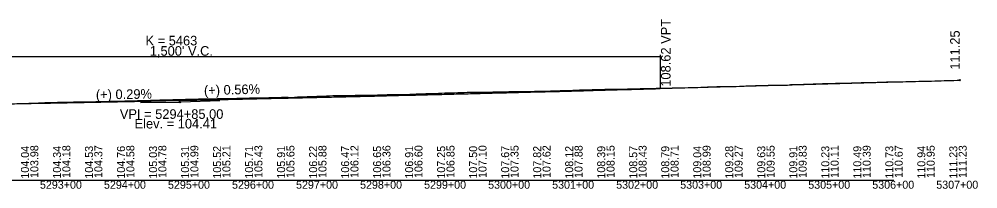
# Model space of a CAD drawing. Extents: x 2121671 to 2169879, y 557274 to 599957.
# Drawn here: x 2158802 to 2160299, y 582173 to 582438 of the extents above; entities that cross this region are included whole.
import ezdxf

# ---------------------------------------------------------------- set-up
doc = ezdxf.new("R2010")
doc.units = 0
for name, color, linetype in [('RD_DDB_GradeTX', 7, 'Continuous'), ('RD_DDB_Profile_EX', 7, 'Continuous'), ('RD_DDB_Profile_Lbl', 7, 'Continuous'), ('RD_DDB_Profile_PR', 7, 'Continuous'), ('RD_DDB_StaTX', 7, 'Continuous'), ('RD_DDB_StripGrade', 7, 'Continuous'), ('RD_DDB_VCLbl', 7, 'Continuous'), ('RD_GPK_Profile_Cell', 7, 'Continuous')]:
    doc.layers.add(name, color=color, linetype=linetype)

msp = doc.modelspace()

# ---------------------------------------------------------------- linework, layer by layer
at = {"layer": 'RD_DDB_GradeTX'}
for p, q in [((2158990.9, 582308), (2159051.9, 582308.9)), ((2159114.9, 582310.6), (2159053.9, 582308.9))]:
    msp.add_line(p, q, dxfattribs=at)
for centre in [(2160270.7, 582343.1), (2159052.9, 582308.9)]:
    msp.add_circle(centre, 1, dxfattribs=at)
at = {"layer": 'RD_DDB_Profile_EX'}
for points in [[(2159986.5, 582335.3), (2159991.5, 582335.2), (2159996.5, 582335.2), (2160001.5, 582335.3), (2160006.5, 582336.1), (2160011.5, 582336.2), (2160016.5, 582336.3), (2160021.5, 582336.5), (2160026.5, 582336.6), (2160031.5, 582336.8), (2160036.5, 582337), (2160041.5, 582337.2), (2160046.5, 582337.3), (2160051.5, 582337.5), (2160056.5, 582337.7), (2160061.5, 582337.8), (2160066.5, 582337.9), (2160071.5, 582338), (2160076.5, 582338.1), (2160081.5, 582338.3), (2160086.5, 582338.4), (2160091.5, 582338.5), (2160096.5, 582338.6), (2160101.5, 582338.7), (2160106.5, 582338.9), (2160111.5, 582338.9), (2160116.5, 582339.2), (2160121.5, 582339.3), (2160126.5, 582339.4), (2160131.5, 582339.5), (2160136.5, 582339.5), (2160141.5, 582339.7), (2160146.5, 582339.9), (2160151.5, 582340), (2160156.5, 582340.2), (2160161.5, 582340.3), (2160166.5, 582340.4), (2160171.5, 582340.5), (2160176.5, 582340.6), (2160181.5, 582340.6), (2160186.5, 582340.7), (2160191.5, 582340.9), (2160196.5, 582341.1), (2160201.5, 582341.2), (2160206.5, 582341.3), (2160211.5, 582341.4), (2160216.5, 582341.5), (2160221.5, 582341.6), (2160226.5, 582341.7), (2160231.5, 582341.9), (2160236.5, 582342.1), (2160241.5, 582342.2), (2160246.5, 582342.3), (2160251.5, 582342.5), (2160256.5, 582342.6), (2160261.5, 582342.7), (2160266.5, 582342.9), (2160270.7, 582343.1)], [(2159486.5, 582323.6), (2159491.5, 582323.7), (2159496.5, 582323.9), (2159501.5, 582324.1), (2159506.5, 582324.2), (2159511.5, 582324.3), (2159516.5, 582324.3), (2159521.5, 582324.3), (2159526.5, 582324.4), (2159531.5, 582324.5), (2159536.5, 582324.5), (2159541.5, 582324.7), (2159546.5, 582325), (2159551.5, 582324.7), (2159556.5, 582324.8), (2159561.5, 582325), (2159566.5, 582325.1), (2159571.5, 582325.3), (2159576.5, 582325.5), (2159581.5, 582325.5), (2159586.5, 582325.1), (2159591.5, 582325.1), (2159596.5, 582325.5), (2159601.5, 582325.5), (2159606.5, 582325.6), (2159611.5, 582325.8), (2159616.5, 582326), (2159621.5, 582325.7), (2159626.5, 582326.1), (2159631.5, 582326.4), (2159636.5, 582326.5), (2159641.5, 582326.6), (2159646.5, 582326.7), (2159651.5, 582326.9), (2159656.5, 582327), (2159661.5, 582327.1), (2159666.5, 582327.4), (2159671.5, 582327.6), (2159676.5, 582327.7), (2159681.5, 582327.9), (2159686.5, 582328), (2159691.5, 582328.2), (2159696.5, 582328.3), (2159701.5, 582328.3), (2159706.5, 582328.4), (2159711.5, 582328.6), (2159716.5, 582328.8), (2159721.5, 582328.8), (2159726.5, 582328.9), (2159731.5, 582329), (2159736.5, 582329), (2159741.5, 582329), (2159746.5, 582329.2), (2159751.5, 582329.4), (2159756.5, 582329.4), (2159761.5, 582329.4), (2159766.5, 582329.6), (2159771.5, 582329.8), (2159776.5, 582329.9), (2159781.5, 582330), (2159786.5, 582330.1), (2159791.5, 582330.2), (2159796.5, 582330.3), (2159801.5, 582330.3), (2159806.5, 582330.4), (2159811.5, 582330.5), (2159816.5, 582330.7), (2159821.5, 582330.9), (2159826.5, 582331), (2159831.5, 582331.1), (2159836.5, 582331.2), (2159841.5, 582331.3), (2159846.5, 582331.4), (2159851.5, 582331.5), (2159856.5, 582331.6), (2159861.5, 582331.8), (2159866.5, 582332), (2159871.5, 582332.2), (2159876.5, 582332.4), (2159881.5, 582332.6), (2159886.5, 582332.8), (2159891.5, 582332.9), (2159896.5, 582333.1), (2159901.5, 582333.3), (2159906.5, 582333.1), (2159911.5, 582333.1), (2159916.5, 582333.2), (2159921.5, 582333.4), (2159926.5, 582333.5), (2159931.5, 582333.9), (2159936.5, 582334.3), (2159941.5, 582334.4), (2159946.5, 582334.3), (2159951.5, 582334.8), (2159956.5, 582334.7), (2159961.5, 582334.8), (2159966.5, 582334.9), (2159971.5, 582335.1), (2159976.5, 582335.3), (2159981.5, 582335.4), (2159986.5, 582335.3)], [(2158801.5, 582306.7), (2158806.5, 582306.8), (2158811.5, 582306.8), (2158816.5, 582307), (2158821.5, 582307.1), (2158826.5, 582307.3), (2158831.5, 582307.5), (2158836.5, 582307.8), (2158841.5, 582308.1), (2158846.5, 582308.3), (2158851.5, 582308.4), (2158856.5, 582308.4), (2158861.5, 582308.5), (2158866.5, 582308.5), (2158871.5, 582308.6), (2158876.5, 582308.8), (2158881.5, 582308.9), (2158886.5, 582309), (2158891.5, 582309.1), (2158896.5, 582309.1), (2158901.5, 582309.4), (2158906.5, 582309.4), (2158911.5, 582309.4), (2158916.5, 582309.4), (2158921.5, 582309.5), (2158926.5, 582309.7), (2158931.5, 582309.9), (2158936.5, 582309.9), (2158941.5, 582310), (2158946.5, 582310.1), (2158951.5, 582310.3), (2158956.5, 582310.3), (2158961.5, 582310.4), (2158966.5, 582310.6), (2158971.5, 582310.8), (2158976.5, 582310.9), (2158981.5, 582311), (2158986.5, 582311.1)], [(2158986.5, 582311.1), (2158991.5, 582311.2), (2158996.5, 582311.3), (2159001.5, 582311.5), (2159006.5, 582311.6), (2159011.5, 582311.7), (2159016.5, 582311.9), (2159021.5, 582312.1), (2159026.5, 582312.2), (2159031.5, 582312.4), (2159036.5, 582312.5), (2159041.5, 582312.6), (2159046.5, 582312.8), (2159051.5, 582312.9), (2159056.5, 582313), (2159061.5, 582313.2), (2159066.5, 582313.4), (2159071.5, 582313.5), (2159076.5, 582313.6), (2159081.5, 582313.7), (2159086.5, 582313.8), (2159091.5, 582313.9), (2159096.5, 582313.9), (2159101.5, 582313.9), (2159106.5, 582314.1), (2159111.5, 582314.3), (2159116.5, 582314.4), (2159121.5, 582314.5), (2159126.5, 582314.5), (2159131.5, 582314.5), (2159136.5, 582314.5), (2159141.5, 582314.7), (2159146.5, 582314.8), (2159151.5, 582315), (2159156.5, 582315.1), (2159161.5, 582315.2), (2159166.5, 582315.4), (2159171.5, 582315.4), (2159176.5, 582315.2), (2159181.5, 582315.2), (2159186.5, 582315.5), (2159191.5, 582315.9), (2159196.5, 582315.9), (2159201.5, 582315.9), (2159206.5, 582316.1), (2159211.5, 582316.3), (2159216.5, 582316.4), (2159221.5, 582316.3), (2159226.5, 582316), (2159231.5, 582316.7), (2159236.5, 582316.9), (2159241.5, 582317.1), (2159246.5, 582317.2), (2159251.5, 582317.3), (2159256.5, 582317.5), (2159261.5, 582317.7), (2159266.5, 582317.9), (2159271.5, 582318.1), (2159276.5, 582318.3), (2159281.5, 582318.5), (2159286.5, 582318.7), (2159291.5, 582318.9), (2159296.5, 582319.1), (2159301.5, 582318.9), (2159306.5, 582318.9), (2159311.5, 582318.9), (2159316.5, 582319.1), (2159321.5, 582319.3), (2159326.5, 582319.4), (2159331.5, 582319.5), (2159336.5, 582319.5), (2159341.5, 582319.5), (2159346.5, 582319.5), (2159351.5, 582319.7), (2159356.5, 582319.8), (2159361.5, 582320), (2159366.5, 582320.1), (2159371.5, 582320.2), (2159376.5, 582320.4), (2159381.5, 582320.5), (2159386.5, 582320.7), (2159391.5, 582320.7), (2159396.5, 582320.6), (2159401.5, 582320.7), (2159406.5, 582320.9), (2159411.5, 582321.1), (2159416.5, 582321.4), (2159421.5, 582321.5), (2159426.5, 582321.7), (2159431.5, 582321.8), (2159436.5, 582322), (2159441.5, 582322.1), (2159446.5, 582322.3), (2159451.5, 582322.4), (2159456.5, 582322.6), (2159461.5, 582322.8), (2159466.5, 582323), (2159471.5, 582323.2), (2159476.5, 582323.3), (2159481.5, 582323.4), (2159486.5, 582323.6)]]:
    msp.add_lwpolyline(points, dxfattribs=at)
at = {"layer": 'RD_DDB_Profile_PR'}
msp.add_line((2159802.9, 582329.9), (2160270.7, 582343.1), dxfattribs=at)
msp.add_spline([(2158302.9, 582298.2), (2158332.9, 582298.6), (2158362.9, 582299), (2158392.9, 582299.5), (2158422.9, 582299.9), (2158452.9, 582300.4), (2158482.9, 582300.9), (2158512.9, 582301.4), (2158542.9, 582301.9), (2158572.9, 582302.4), (2158602.9, 582302.9), (2158632.9, 582303.4), (2158662.9, 582303.9), (2158692.9, 582304.4), (2158722.9, 582305), (2158752.9, 582305.5), (2158782.9, 582306.1), (2158812.9, 582306.7), (2158842.9, 582307.2), (2158872.9, 582307.8), (2158902.9, 582308.4), (2158932.9, 582309), (2158962.9, 582309.6), (2158992.9, 582310.2), (2159022.9, 582310.8), (2159052.9, 582311.5), (2159082.9, 582312.1), (2159112.9, 582312.8), (2159142.9, 582313.4), (2159172.9, 582314.1), (2159202.9, 582314.8), (2159232.9, 582315.4), (2159262.9, 582316.1), (2159292.9, 582316.8), (2159322.9, 582317.5), (2159352.9, 582318.2), (2159382.9, 582319), (2159412.9, 582319.7), (2159442.9, 582320.4), (2159472.9, 582321.2), (2159502.9, 582321.9), (2159532.9, 582322.7), (2159562.9, 582323.5), (2159592.9, 582324.3), (2159622.9, 582325), (2159652.9, 582325.8), (2159682.9, 582326.6), (2159712.9, 582327.5), (2159742.9, 582328.3), (2159772.9, 582329.1), (2159802.9, 582329.9)], degree=3, dxfattribs=at)
at = {"layer": 'RD_DDB_VCLbl'}
for p, q in [((2158302.9, 582379.9), (2159802.9, 582379.9)), ((2159802.9, 582382.4), (2159802.9, 582329.9))]:
    msp.add_line(p, q, dxfattribs=at)
at = {"layer": 'RD_GPK_Profile_Cell'}
msp.add_line((2157367.9, 582186.8), (2160167.9, 582186.8), dxfattribs=at)

# ---------------------------------------------------------------- texts
at = {"layer": 'RD_DDB_GradeTX'}
for s, rotation, p in [('(+) 0.29%', 0.8206, (2158921.5, 582313)), ('(+) 0.56%', 1.6068, (2159090.4, 582319.5))]:
    msp.add_text(s, height=15, rotation=rotation, dxfattribs=at).set_placement(p)
at = {"layer": 'RD_DDB_Profile_Lbl'}
msp.add_text('111.25', height=15, rotation=90, dxfattribs=at).set_placement((2160270.7, 582359.4))
for s, p in [('VPI = 5294+85.00', (2158958.8, 582282.6)), ('Elev. = 104.41', (2158981.8, 582267.6))]:
    msp.add_text(s, height=15, dxfattribs=at).set_placement(p)
at = {"layer": 'RD_DDB_StaTX'}
for s, p in [('5293+00', (2158834, 582173.5)), ('5294+00', (2158934, 582173.5)), ('5295+00', (2159034, 582173.5)), ('5296+00', (2159134, 582173.5)), ('5297+00', (2159234, 582173.5)), ('5298+00', (2159334, 582173.5)), ('5299+00', (2159434, 582173.5)), ('5300+00', (2159534, 582173.5)), ('5301+00', (2159634, 582173.5)), ('5302+00', (2159734, 582173.5)), ('5303+00', (2159834, 582173.5)), ('5304+00', (2159934, 582173.5)), ('5305+00', (2160034, 582173.5)), ('5306+00', (2160134, 582173.5)), ('5307+00', (2160234, 582173.5))]:
    msp.add_text(s, height=12.5, dxfattribs=at).set_placement(p)
at = {"layer": 'RD_DDB_StripGrade'}
for s, height, p in [('108.62 VPT', 15, (2159819, 582332.8)), ('104.04', 12.5, (2158816.9, 582189.3)), ('103.98', 12.5, (2158831.5, 582190.3)), ('104.34', 12.5, (2158866.9, 582189.3)), ('104.18', 12.5, (2158881.5, 582190.3)), ('104.53', 12.5, (2158916.9, 582189.3)), ('104.37', 12.5, (2158931.5, 582190.3)), ('104.76', 12.5, (2158966.9, 582189.3)), ('104.58', 12.5, (2158981.5, 582190.3)), ('105.03', 12.5, (2159016.9, 582189.3)), ('104.78', 12.5, (2159031.5, 582190.3)), ('105.31', 12.5, (2159066.9, 582189.3)), ('104.99', 12.5, (2159081.5, 582190.3)), ('105.52', 12.5, (2159116.9, 582189.3)), ('105.21', 12.5, (2159131.5, 582190.3)), ('105.71', 12.5, (2159166.9, 582189.3)), ('105.43', 12.5, (2159181.5, 582190.3)), ('105.91', 12.5, (2159216.9, 582189.3)), ('105.65', 12.5, (2159231.5, 582190.3)), ('106.22', 12.5, (2159266.9, 582189.3)), ('105.88', 12.5, (2159281.5, 582190.3)), ('106.47', 12.5, (2159316.9, 582189.3)), ('106.12', 12.5, (2159331.5, 582190.3)), ('106.65', 12.5, (2159366.9, 582189.3)), ('106.36', 12.5, (2159381.5, 582190.3)), ('106.91', 12.5, (2159416.9, 582189.3)), ('106.60', 12.5, (2159431.5, 582190.3)), ('107.25', 12.5, (2159466.9, 582189.3)), ('106.85', 12.5, (2159481.5, 582190.3)), ('107.50', 12.5, (2159516.9, 582189.3)), ('107.10', 12.5, (2159531.5, 582190.3)), ('107.67', 12.5, (2159566.9, 582189.3)), ('107.35', 12.5, (2159581.5, 582190.3)), ('107.82', 12.5, (2159616.9, 582189.3)), ('107.62', 12.5, (2159631.5, 582190.3)), ('108.12', 12.5, (2159666.9, 582189.3)), ('107.88', 12.5, (2159681.5, 582190.3)), ('108.39', 12.5, (2159716.9, 582189.3)), ('108.15', 12.5, (2159731.5, 582190.3)), ('108.57', 12.5, (2159766.9, 582189.3)), ('108.43', 12.5, (2159781.5, 582190.3)), ('108.79', 12.5, (2159816.9, 582189.3)), ('108.71', 12.5, (2159831.5, 582190.3)), ('109.04', 12.5, (2159866.9, 582189.3)), ('108.99', 12.5, (2159881.5, 582190.3)), ('109.28', 12.5, (2159916.9, 582189.3)), ('109.27', 12.5, (2159931.5, 582190.3)), ('109.63', 12.5, (2159966.9, 582189.3)), ('109.55', 12.5, (2159981.5, 582190.3)), ('109.91', 12.5, (2160016.9, 582189.3)), ('109.83', 12.5, (2160031.5, 582190.3)), ('110.23', 12.5, (2160066.9, 582189.3)), ('110.11', 12.5, (2160081.5, 582190.3)), ('110.49', 12.5, (2160116.9, 582189.3)), ('110.39', 12.5, (2160131.5, 582190.3)), ('110.73', 12.5, (2160166.9, 582189.3)), ('110.67', 12.5, (2160181.5, 582190.3)), ('110.94', 12.5, (2160216.9, 582189.3)), ('110.95', 12.5, (2160231.5, 582190.3)), ('111.23', 12.5, (2160266.9, 582189.3)), ('111.23', 12.5, (2160281.5, 582190.3))]:
    msp.add_text(s, height=height, rotation=90, dxfattribs=at).set_placement(p)
at = {"layer": 'RD_DDB_VCLbl'}
for s, p in [('K = 5463', (2158998.9, 582397.3)), ("1,500' V.C.", (2159005.6, 582381.2))]:
    msp.add_text(s, height=15, dxfattribs=at).set_placement(p)

doc.saveas('drawing.dxf')
